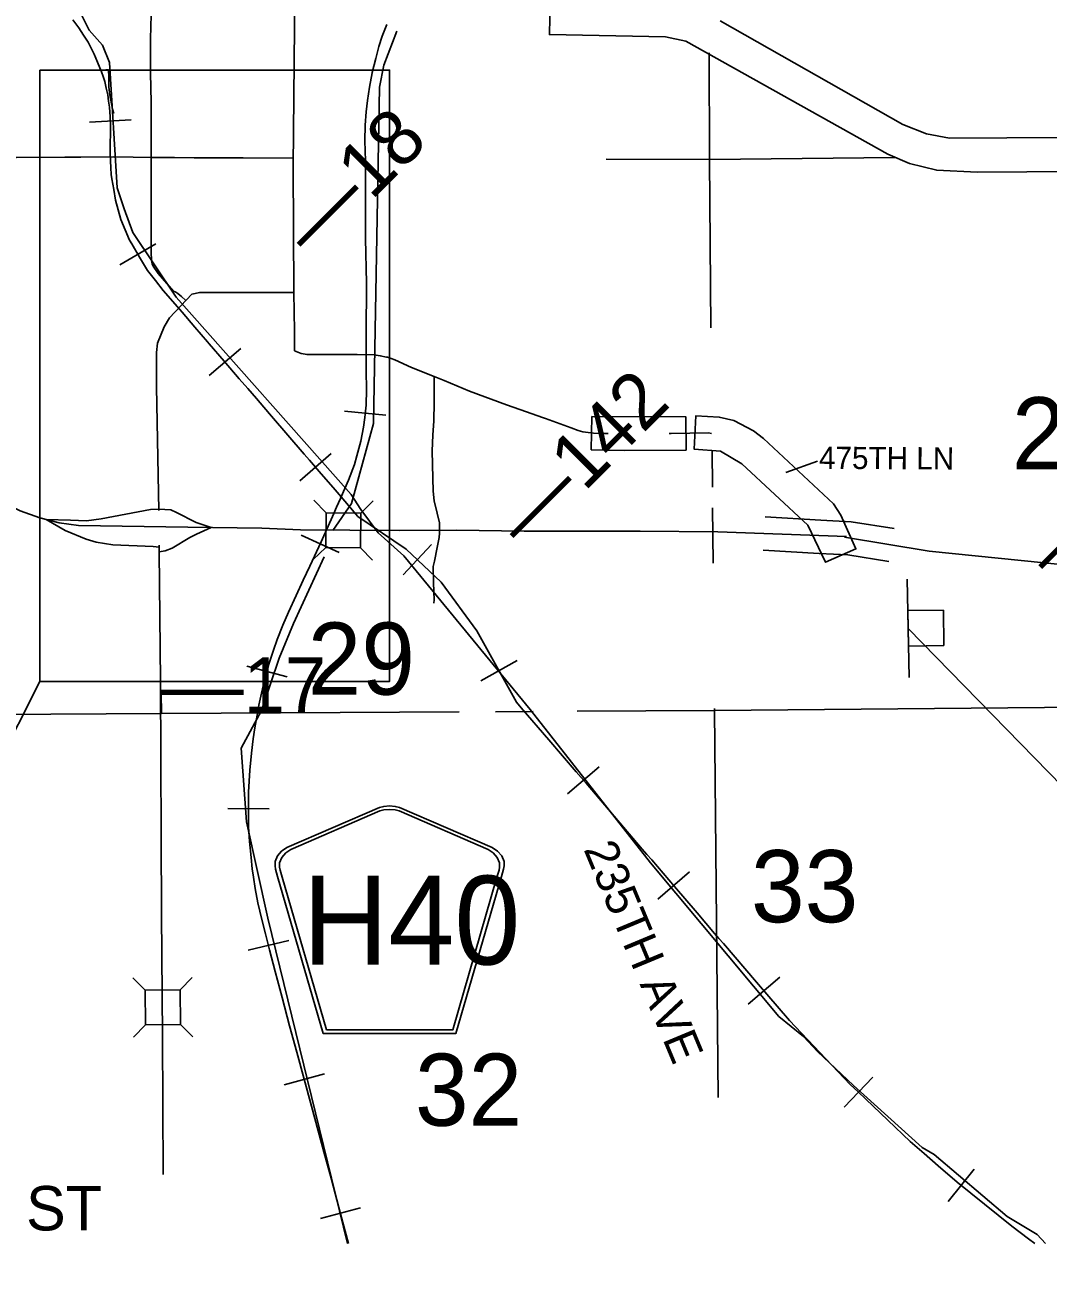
# Model space of a CAD drawing. Extents: x 10133 to 81668, y 5524 to 11018.
# Drawn here: x 18489.8 to 18720.3, y 8198.3 to 8478.4 of the extents above; entities that cross this region are included whole.
import ezdxf

# ---------------------------------------------------------------- set-up
doc = ezdxf.new("R2010")
doc.units = 0
for name, color, linetype in [('Default', 7, 'Continuous'), ('DisBoundDim', 7, 'Continuous'), ('DisCLMLOR', 7, 'Continuous'), ('DisCLMLSUR', 7, 'Continuous'), ('DsnShtRevisedText', 7, 'Continuous'), ('trf_Signal_(Temp)_Layout', 7, 'Continuous')]:
    doc.layers.add(name, color=color, linetype=linetype)

msp = doc.modelspace()

# ---------------------------------------------------------------- linework, layer by layer
at = {"layer": 'Default'}
for p, q in [((18504.33, 8456.54), (18513.69, 8457.07)), ((18511.2, 8424.34), (18519.28, 8429.08)), ((18531.29, 8399.4), (18538.41, 8405.51)), ((18571.11, 8390.47), (18561.78, 8391.37)), ((18551.72, 8375.73), (18558.81, 8381.86)), ((18661.23, 8377.6), (18668.35, 8380.11)), ((18557.64, 8368.53), (18554.91, 8371.33)), ((18559.14, 8364.52), (18563.36, 8370.6)), ((18559.14, 8364.52), (18563.36, 8370.6)), ((18565.47, 8368.44), (18568.26, 8371.18)), ((18560.57, 8359.59), (18552.05, 8363.49)), ((18557.56, 8360.7), (18554.76, 8357.97)), ((18574.99, 8354.52), (18581.4, 8361.36)), ((18565.38, 8360.62), (18568.12, 8357.82)), ((18548.83, 8331.54), (18539.77, 8333.95)), ((18592.5, 8330.65), (18600.69, 8335.22)), ((18612.02, 8305.22), (18619.15, 8311.31)), ((18544.84, 8301.82), (18535.47, 8301.9)), ((18632.36, 8281.49), (18639.48, 8287.59)), ((18549.21, 8272.16), (18540.1, 8269.94)), ((18516.91, 8260.98), (18514.12, 8263.72)), ((18524.73, 8261.04), (18527.48, 8263.83)), ((18652.73, 8257.77), (18659.84, 8263.89)), ((18516.97, 8253.15), (18514.23, 8250.36)), ((18524.8, 8253.22), (18527.59, 8250.47)), ((18557.24, 8242.1), (18548.2, 8239.62)), ((18674.32, 8234.57), (18680.8, 8241.35)), ((18697.77, 8213.34), (18703.66, 8220.64)), ((18565.4, 8211.89), (18556.34, 8209.49))]:
    msp.add_line(p, q, dxfattribs=at)
for points in [[(18549.96, 8829.52), (18550.05, 8805.91), (18550.08, 8784.02), (18550.7, 8682.54), (18550.52, 8671.29), (18550.52, 8648.11), (18550.42, 8612.38), (18550.55, 8600.55), (18550.42, 8588.37), (18550.39, 8561.4), (18550.49, 8516.33), (18550.49, 8477.93), (18550.25, 8446.49), (18550.39, 8418.13), (18529.16, 8418.16), (18527.4, 8417.73), (18522.35, 8412.45), (18521.12, 8410.42), (18519.69, 8406.72), (18519.42, 8404.63), (18519.45, 8396.89), (18519.92, 8368.99)], [(18377.81, 8580.32), (18418.01, 8548.19), (18499.93, 8484.11), (18502.3, 8481.16), (18504.29, 8477.22), (18507.26, 8473.87), (18508.86, 8469.93), (18510.53, 8441.72), (18512.12, 8436.99), (18514.11, 8431.67), (18523.83, 8417.09), (18563.25, 8372.62), (18565.44, 8369.27), (18569.4, 8363.96), (18575.14, 8358.84), (18603.64, 8324.17)], [(18377.81, 8580.32), (18418.01, 8548.19), (18499.93, 8484.11), (18502.3, 8481.16), (18504.29, 8477.22), (18507.26, 8473.87), (18508.86, 8469.93), (18510.53, 8441.72), (18512.12, 8436.99), (18514.11, 8431.67), (18523.83, 8417.09), (18563.25, 8372.62), (18565.44, 8369.27), (18569.4, 8363.96), (18575.14, 8358.84), (18603.64, 8324.17)], [(18816.05, 8445.98), (18704.28, 8445.21), (18695.21, 8445.66), (18689.09, 8447.21), (18684.18, 8449.31), (18638.68, 8474.75), (18634.09, 8475.7), (18607.96, 8476.25), (18608.14, 8483.75)], [(18646.39, 8479.35), (18687.6, 8455.98), (18692.87, 8453.87), (18698.1, 8452.88), (18827.11, 8453.63), (18830.92, 8454.32), (18837.18, 8457.2), (18882.24, 8482.55)], [(18500.59, 8479.53), (18501.96, 8477.75), (18502.99, 8476.14), (18504.02, 8474.54), (18504.71, 8473.19), (18505.4, 8471.85), (18506.16, 8469.99), (18507.03, 8467.88), (18507.39, 8466.79), (18507.76, 8465.7), (18508.11, 8464.17), (18508.46, 8462.64), (18508.65, 8461.27), (18508.84, 8459.9), (18508.96, 8457.69), (18509.09, 8455.48), (18509.03, 8453.42), (18509, 8452.26), (18508.96, 8451.09), (18509, 8449.43), (18509.04, 8447.78), (18509.13, 8446.23), (18509.21, 8444.69), (18509.37, 8443.76), (18509.78, 8441.36), (18510.19, 8438.96), (18510.81, 8436.78), (18511.42, 8434.6), (18512.39, 8432.26), (18513.36, 8429.93), (18513.84, 8429.09), (18515.61, 8426.08), (18517.37, 8423.07), (18519.17, 8420.84), (18520.96, 8418.6), (18524.18, 8414.94), (18524.69, 8414.31), (18525.21, 8413.68), (18528.07, 8410.35), (18530.94, 8407.01), (18531.33, 8406.55), (18534.69, 8402.64), (18538.06, 8398.72), (18540, 8396.5), (18541.95, 8394.28), (18543.63, 8392.29), (18545.31, 8390.31), (18549.01, 8386.03), (18552.71, 8381.75), (18553.9, 8380.37), (18556.56, 8377.29), (18559.22, 8374.22), (18560.12, 8373.15), (18561.02, 8372.09), (18564.75, 8367.68), (18575.7, 8360.28), (18583.59, 8352.89), (18591.57, 8341.93), (18600.56, 8325.83), (18601.6, 8324.59), (18607.8, 8317.36), (18614, 8310.13), (18616.19, 8307.56), (18622.51, 8300.16), (18628.84, 8292.75), (18629.92, 8291.52), (18631, 8290.29), (18636.1, 8284.33), (18641.2, 8278.37), (18643.18, 8276.06), (18645.16, 8273.75), (18646.15, 8272.61), (18647.14, 8271.46), (18654.6, 8262.79), (18662.05, 8254.12), (18668.89, 8246.91), (18675.73, 8239.71), (18677.47, 8238.05), (18679.2, 8236.39), (18684.21, 8231.65), (18689.22, 8226.9), (18692.38, 8224.14), (18695.54, 8221.38), (18699.79, 8217.74), (18705.95, 8212.77), (18712.11, 8207.8), (18715.88, 8204.97), (18717.33, 8203.88)], [(18500.59, 8479.53), (18501.96, 8477.75), (18502.99, 8476.14), (18504.02, 8474.54), (18504.71, 8473.19), (18505.4, 8471.85), (18506.16, 8469.99), (18507.03, 8467.88), (18507.39, 8466.79), (18507.76, 8465.7), (18508.11, 8464.17), (18508.46, 8462.64), (18508.65, 8461.27), (18508.84, 8459.9), (18508.96, 8457.69), (18509.09, 8455.48), (18509.03, 8453.42), (18509, 8452.26), (18508.96, 8451.09), (18509, 8449.43), (18509.04, 8447.78), (18509.13, 8446.23), (18509.21, 8444.69), (18509.37, 8443.76), (18509.78, 8441.36), (18510.19, 8438.96), (18510.81, 8436.78), (18511.42, 8434.6), (18512.39, 8432.26), (18513.36, 8429.93), (18513.84, 8429.09), (18515.61, 8426.08), (18517.37, 8423.07), (18519.17, 8420.84), (18520.96, 8418.6), (18524.18, 8414.94), (18524.69, 8414.31), (18525.21, 8413.68), (18528.07, 8410.35), (18530.94, 8407.01), (18531.33, 8406.55), (18534.69, 8402.64), (18538.06, 8398.72), (18540, 8396.5), (18541.95, 8394.28), (18543.63, 8392.29), (18545.31, 8390.31), (18549.01, 8386.03), (18552.71, 8381.75), (18553.9, 8380.37), (18556.56, 8377.29), (18559.22, 8374.22), (18560.12, 8373.15), (18561.02, 8372.09), (18564.75, 8367.68), (18575.7, 8360.28), (18583.59, 8352.89), (18591.57, 8341.93), (18600.56, 8325.83), (18601.6, 8324.59), (18607.8, 8317.36), (18614, 8310.13), (18616.19, 8307.56), (18622.51, 8300.16), (18628.84, 8292.75), (18629.92, 8291.52), (18631, 8290.29), (18636.1, 8284.33), (18641.2, 8278.37), (18643.18, 8276.06), (18645.16, 8273.75), (18646.15, 8272.61), (18647.14, 8271.46), (18654.6, 8262.79), (18662.05, 8254.12), (18668.89, 8246.91), (18675.73, 8239.71), (18677.47, 8238.05), (18679.2, 8236.39), (18684.21, 8231.65), (18689.22, 8226.9), (18692.38, 8224.14), (18695.54, 8221.38), (18699.79, 8217.74), (18705.95, 8212.77), (18712.11, 8207.8), (18715.88, 8204.97), (18717.33, 8203.88)], [(18500.59, 8479.53), (18501.96, 8477.75), (18502.99, 8476.14), (18504.02, 8474.54), (18504.71, 8473.19), (18505.4, 8471.85), (18506.16, 8469.99), (18507.03, 8467.88), (18507.39, 8466.79), (18507.76, 8465.7), (18508.11, 8464.17), (18508.46, 8462.64), (18508.65, 8461.27), (18508.84, 8459.9), (18508.96, 8457.69), (18509.09, 8455.48), (18509.03, 8453.42), (18509, 8452.26), (18508.96, 8451.09), (18509, 8449.43), (18509.04, 8447.78), (18509.13, 8446.23), (18509.21, 8444.69), (18509.37, 8443.76), (18509.78, 8441.36), (18510.19, 8438.96), (18510.81, 8436.78), (18511.42, 8434.6), (18512.39, 8432.26), (18513.36, 8429.93), (18513.84, 8429.09), (18515.61, 8426.08), (18517.37, 8423.07), (18519.17, 8420.84), (18520.96, 8418.6), (18524.18, 8414.94), (18524.69, 8414.31), (18525.21, 8413.68), (18528.07, 8410.35), (18530.94, 8407.01), (18531.33, 8406.55), (18534.69, 8402.64), (18538.06, 8398.72), (18540, 8396.5), (18541.95, 8394.28), (18543.63, 8392.29), (18545.31, 8390.31), (18549.01, 8386.03), (18552.71, 8381.75), (18553.9, 8380.37), (18556.56, 8377.29), (18559.22, 8374.22), (18560.12, 8373.15), (18561.02, 8372.09), (18564.75, 8367.68), (18575.7, 8360.28), (18583.59, 8352.89), (18591.57, 8341.93), (18600.56, 8325.83), (18601.6, 8324.59), (18607.8, 8317.36), (18614, 8310.13), (18616.19, 8307.56), (18622.51, 8300.16), (18628.84, 8292.75), (18629.92, 8291.52), (18631, 8290.29), (18636.1, 8284.33), (18641.2, 8278.37), (18643.18, 8276.06), (18645.16, 8273.75), (18646.15, 8272.61), (18647.14, 8271.46), (18654.6, 8262.79), (18662.05, 8254.12), (18668.89, 8246.91), (18675.73, 8239.71), (18677.47, 8238.05), (18679.2, 8236.39), (18684.21, 8231.65), (18689.22, 8226.9), (18692.38, 8224.14), (18695.54, 8221.38), (18699.79, 8217.74), (18705.95, 8212.77), (18712.11, 8207.8), (18715.88, 8204.97), (18717.33, 8203.88)], [(18518.23, 8448.58), (18518.2, 8456.57), (18518.2, 8458.37), (18518.2, 8460.95), (18518.11, 8467.64), (18518.11, 8468.24), (18518.05, 8475.25), (18518.21, 8480.66)], [(18562.65, 8203.88), (18560.89, 8210.6), (18558.86, 8218.27), (18557.32, 8223.68), (18554.37, 8234.82), (18551.03, 8247.01), (18549.42, 8252.94), (18547.75, 8259.33), (18546.15, 8265.2), (18544.9, 8270.04), (18544.02, 8273.68), (18543.16, 8276.89), (18542.28, 8280.6), (18541.69, 8283.87), (18541.26, 8286.4), (18540.97, 8288.33), (18540.74, 8290.82), (18540.41, 8294.46), (18540.18, 8297.73), (18540.15, 8301.5), (18540.18, 8305.57), (18540.45, 8310.55), (18540.84, 8314.38), (18541.2, 8317.59), (18541.56, 8320.08), (18542.08, 8322.93), (18542.48, 8325.16), (18543.07, 8327.85), (18543.79, 8330.83), (18544.74, 8334.4), (18545.75, 8337.55), (18546.64, 8339.94), (18547.92, 8343.22), (18549.19, 8346.13), (18550.87, 8349.87), (18552.44, 8353.32), (18553.98, 8356.45), (18556.5, 8361.96), (18559.36, 8368.32), (18560.01, 8369.76), (18560.86, 8371.7), (18561.02, 8372.09), (18562.66, 8375.85), (18564.01, 8379.36), (18564.59, 8381.32), (18565.45, 8384.63), (18566.04, 8387.81), (18566.33, 8389.99), (18566.43, 8390.73), (18566.63, 8392.76), (18566.76, 8396.27), (18566.69, 8400.46), (18566.66, 8403.64), (18566.66, 8408.36), (18566.66, 8411.37), (18566.73, 8417.47), (18566.76, 8420.22), (18566.53, 8430.31), (18566.53, 8433.33), (18566.51, 8441.6), (18566.5, 8447.78), (18566.4, 8452.27), (18566.43, 8455.81), (18566.66, 8458.82), (18566.95, 8461.38), (18567.41, 8464.36), (18568.02, 8467.64), (18568.04, 8467.7), (18568.82, 8470.85), (18569.51, 8473.57), (18570.3, 8475.89), (18571.35, 8478.51)], [(18562.65, 8203.88), (18560.89, 8210.6), (18558.86, 8218.27), (18557.32, 8223.68), (18554.37, 8234.82), (18551.03, 8247.01), (18549.42, 8252.94), (18547.75, 8259.33), (18546.15, 8265.2), (18544.9, 8270.04), (18544.02, 8273.68), (18543.16, 8276.89), (18542.28, 8280.6), (18541.69, 8283.87), (18541.26, 8286.4), (18540.97, 8288.33), (18540.74, 8290.82), (18540.41, 8294.46), (18540.18, 8297.73), (18540.15, 8301.5), (18540.18, 8305.57), (18540.45, 8310.55), (18540.84, 8314.38), (18541.2, 8317.59), (18541.56, 8320.08), (18542.08, 8322.93), (18542.48, 8325.16), (18543.07, 8327.85), (18543.79, 8330.83), (18544.74, 8334.4), (18545.75, 8337.55), (18546.64, 8339.94), (18547.92, 8343.22), (18549.19, 8346.13), (18550.87, 8349.87), (18552.44, 8353.32), (18553.98, 8356.45), (18556.5, 8361.96), (18559.36, 8368.32), (18560.01, 8369.76), (18560.86, 8371.7), (18561.02, 8372.09), (18562.66, 8375.85), (18564.01, 8379.36), (18564.59, 8381.32), (18565.45, 8384.63), (18566.04, 8387.81), (18566.33, 8389.99), (18566.43, 8390.73), (18566.63, 8392.76), (18566.76, 8396.27), (18566.69, 8400.46), (18566.66, 8403.64), (18566.66, 8408.36), (18566.66, 8411.37), (18566.73, 8417.47), (18566.76, 8420.22), (18566.53, 8430.31), (18566.53, 8433.33), (18566.51, 8441.6), (18566.5, 8447.78), (18566.4, 8452.27), (18566.43, 8455.81), (18566.66, 8458.82), (18566.95, 8461.38), (18567.41, 8464.36), (18568.02, 8467.64), (18568.04, 8467.7), (18568.82, 8470.85), (18569.51, 8473.57), (18570.3, 8475.89), (18571.35, 8478.51)], [(18562.65, 8203.88), (18560.89, 8210.6), (18558.86, 8218.27), (18557.32, 8223.68), (18554.37, 8234.82), (18551.03, 8247.01), (18549.42, 8252.94), (18547.75, 8259.33), (18546.15, 8265.2), (18544.9, 8270.04), (18544.02, 8273.68), (18543.16, 8276.89), (18542.28, 8280.6), (18541.69, 8283.87), (18541.26, 8286.4), (18540.97, 8288.33), (18540.74, 8290.82), (18540.41, 8294.46), (18540.18, 8297.73), (18540.15, 8301.5), (18540.18, 8305.57), (18540.45, 8310.55), (18540.84, 8314.38), (18541.2, 8317.59), (18541.56, 8320.08), (18542.08, 8322.93), (18542.48, 8325.16), (18543.07, 8327.85), (18543.79, 8330.83), (18544.74, 8334.4), (18545.75, 8337.55), (18546.64, 8339.94), (18547.92, 8343.22), (18549.19, 8346.13), (18550.87, 8349.87), (18552.44, 8353.32), (18553.98, 8356.45), (18556.5, 8361.96), (18559.36, 8368.32), (18560.01, 8369.76), (18560.86, 8371.7), (18561.02, 8372.09), (18562.66, 8375.85), (18564.01, 8379.36), (18564.59, 8381.32), (18565.45, 8384.63), (18566.04, 8387.81), (18566.33, 8389.99), (18566.43, 8390.73), (18566.63, 8392.76), (18566.76, 8396.27), (18566.69, 8400.46), (18566.66, 8403.64), (18566.66, 8408.36), (18566.66, 8411.37), (18566.73, 8417.47), (18566.76, 8420.22), (18566.53, 8430.31), (18566.53, 8433.33), (18566.51, 8441.6), (18566.5, 8447.78), (18566.4, 8452.27), (18566.43, 8455.81), (18566.66, 8458.82), (18566.95, 8461.38), (18567.41, 8464.36), (18568.02, 8467.64), (18568.04, 8467.7), (18568.82, 8470.85), (18569.51, 8473.57), (18570.3, 8475.89), (18571.35, 8478.51)], [(18563.36, 8370.6), (18568.33, 8388.62), (18569.66, 8464.4), (18570.63, 8469.33), (18573.57, 8477.04)], [(18563.36, 8370.6), (18568.33, 8388.62), (18569.66, 8464.4), (18570.63, 8469.33), (18573.57, 8477.04)], [(18643.93, 8472.13), (18643.98, 8448.12)], [(18508, 8468.27), (18508.62, 8468.27)], [(18509.8, 8458.44), (18509.49, 8459.45), (18508.91, 8462.66), (18508.66, 8464.42), (18508.66, 8466.67), (18508.62, 8468.27)], [(18458.15, 8448.9), (18467.2, 8448.77), (18468.06, 8448.76), (18468.88, 8448.75), (18479.25, 8448.66), (18487.78, 8448.58), (18487.91, 8448.58), (18498.78, 8448.63), (18502.4, 8448.65), (18509.8, 8448.68), (18514.2, 8448.63), (18518.23, 8448.58)], [(18526.03, 8416.33), (18525.09, 8417.2), (18524.66, 8417.56), (18524.22, 8417.9), (18523.75, 8418.2), (18523.27, 8418.47), (18519.82, 8422.44), (18518.67, 8424.05), (18518.42, 8424.6), (18518.33, 8425.37), (18518.2, 8427.26), (18518.21, 8428.91), (18518.23, 8432.93), (18518.2, 8437.15), (18518.21, 8438.67), (18518.23, 8447.69), (18518.23, 8448.58)], [(18518.23, 8448.58), (18523.52, 8448.52), (18527.95, 8448.51), (18534.12, 8448.5), (18537.78, 8448.49), (18538.99, 8448.49), (18550.25, 8448.4), (18550.25, 8448.4)], [(18620.73, 8448.18), (18643.98, 8448.12)], [(18643.98, 8448.12), (18685.75, 8448.57)], [(18643.98, 8448.12), (18644.33, 8410.2)], [(18550.38, 8418.13), (18550.38, 8418.13), (18550.49, 8409.39), (18550.52, 8407.18), (18550.53, 8405.03), (18552.03, 8404.41), (18553.36, 8404.13), (18555.7, 8404.13), (18561.12, 8404.13), (18564.67, 8404.13), (18568.49, 8404.1), (18569.82, 8403.89), (18571.28, 8403.58), (18571.45, 8403.55), (18573.15, 8402.99), (18576.88, 8401.24), (18581.97, 8399.2)], [(18581.92, 8348.13), (18581.98, 8348.91), (18581.98, 8348.93), (18581.8, 8352.72), (18581.77, 8356.39), (18582.04, 8357.59), (18582.66, 8360.67), (18583.09, 8362.92), (18583.18, 8363.94), (18583.18, 8364.59), (18583.15, 8366.22), (18582.69, 8368.44), (18582.01, 8371.21), (18581.77, 8373.37), (18581.67, 8376.27), (18581.52, 8382.5), (18581.67, 8385.98), (18581.89, 8389.25), (18581.91, 8389.89), (18581.98, 8392.67), (18582.01, 8398.65), (18581.97, 8399.2)], [(18581.97, 8399.2), (18584.21, 8398.31), (18589.92, 8395.9), (18598.27, 8392.85), (18602.78, 8391.27), (18606.4, 8390), (18607.06, 8389.77), (18612.81, 8387.62), (18614.39, 8387.02), (18615.5, 8386.72), (18617.88, 8386.44), (18620.18, 8386.4), (18621.19, 8386.38)], [(18624.9, 8382.57), (18617.39, 8382.7), (18617.53, 8390.19), (18638.68, 8390.15), (18638.72, 8382.65), (18624.9, 8382.57)], [(18666.17, 8365.69), (18651.3, 8379.5), (18646.47, 8382.37), (18640.58, 8382.83), (18640.93, 8390.32), (18646.21, 8390.07), (18649.51, 8389.28), (18653.9, 8387), (18656.15, 8385.22), (18671.91, 8370.51), (18673.63, 8367.99), (18677.01, 8360.38), (18670.15, 8357.35), (18666.17, 8365.69)], [(18634.95, 8386.37), (18635.36, 8386.38), (18643.77, 8386.5), (18644.5, 8386.4)], [(18644.58, 8382.65), (18644.66, 8374.26)], [(18519.96, 8369.29), (18518.11, 8369.25), (18506.94, 8367.13), (18503.69, 8366.7), (18500.05, 8366.82), (18494.59, 8366.99)], [(18531.71, 8365.22), (18528.35, 8366.35), (18523.9, 8368.6), (18522.63, 8369.14), (18519.96, 8369.29)], [(18644.71, 8369.64), (18644.82, 8357.15)], [(18494.6, 8366.99), (18498.87, 8364.48), (18503.59, 8362.6), (18505.81, 8361.92), (18509.62, 8361.31), (18518.69, 8360.92), (18520.05, 8360.79)], [(18656.54, 8367.58), (18669.11, 8366.83), (18675.96, 8366.46), (18685.64, 8364.96)], [(18520.06, 8359.69), (18521.35, 8359.91), (18522.97, 8360.52), (18526.97, 8362.96), (18528.47, 8363.69), (18531.71, 8365.22)], [(18656.34, 8363.87), (18656.33, 8363.87)], [(18543.06, 8323.99), (18547.09, 8335.78), (18550.32, 8343.57), (18557.18, 8358.59)], [(18543.06, 8323.99), (18547.09, 8335.78), (18550.32, 8343.57), (18557.18, 8358.59)], [(18656.13, 8360.09), (18668.72, 8359.33), (18675.19, 8359), (18684.38, 8357.56)], [(18520.48, 8327.97), (18520.57, 8323.3)], [(18645.12, 8324.41), (18645.13, 8323.93)], [(18645.13, 8323.93), (18769.03, 8325.06)], [(18395.75, 8322.57), (18520.57, 8323.3)], [(18520.57, 8323.3), (18587.64, 8323.64)], [(18562.49, 8203.88), (18544.54, 8277.19), (18539.74, 8298.89), (18538.51, 8315.46), (18543.06, 8323.99)], [(18562.49, 8203.88), (18544.54, 8277.19), (18539.74, 8298.89), (18538.51, 8315.46), (18543.06, 8323.99)], [(18595.77, 8323.68), (18604.31, 8323.73)], [(18603.64, 8324.17), (18630.74, 8289.68), (18659.65, 8255.04), (18665.18, 8250.52), (18668.35, 8247.17), (18676.46, 8239.5), (18691.89, 8225.53), (18694.66, 8223.96), (18711.08, 8210), (18717.8, 8205.88), (18719.7, 8203.88)], [(18603.64, 8324.17), (18630.74, 8289.68), (18659.65, 8255.04), (18665.18, 8250.52), (18668.35, 8247.17), (18676.46, 8239.5), (18691.89, 8225.53), (18694.66, 8223.96), (18711.08, 8210), (18717.8, 8205.88), (18719.7, 8203.88)], [(18614.19, 8323.78), (18645.13, 8323.93)], [(18645.93, 8236.79), (18645.13, 8323.93)]]:
    msp.add_lwpolyline(points, dxfattribs=at)
for points in [[(18557.64, 8368.53), (18565.47, 8368.44), (18565.38, 8360.62), (18557.56, 8360.7)], [(18556.96, 8251.2), (18546.72, 8286.56), (18546.23, 8288.21), (18546.14, 8288.94), (18546.14, 8289.92), (18546.67, 8291.21), (18547.58, 8292.27), (18548.78, 8293.11), (18569.69, 8302.15), (18570.63, 8302.35), (18571.93, 8302.47), (18573.23, 8302.35), (18574.17, 8302.15), (18595.08, 8293.11), (18596.28, 8292.27), (18597.19, 8291.21), (18597.72, 8289.92), (18597.72, 8288.94), (18597.63, 8288.21), (18597.14, 8286.56), (18586.9, 8251.2)], [(18557.69, 8251.99), (18547.73, 8286.4), (18547.26, 8287.98), (18547.17, 8288.69), (18547.17, 8289.63), (18547.68, 8290.86), (18548.55, 8291.88), (18549.7, 8292.68), (18569.78, 8301.36), (18570.68, 8301.56), (18571.93, 8301.67), (18573.18, 8301.56), (18574.08, 8301.36), (18594.16, 8292.68), (18595.3, 8291.88), (18596.18, 8290.86), (18596.69, 8289.63), (18596.69, 8288.69), (18596.6, 8287.98), (18596.13, 8286.4), (18586.17, 8251.99)], [(18516.97, 8253.15), (18516.91, 8260.98), (18524.73, 8261.04), (18524.8, 8253.22)]]:
    msp.add_lwpolyline(points, close=True, dxfattribs=at)
at = {"layer": 'DisBoundDim'}
for p, q in [((18688.58, 8353.53), (18688.96, 8331.4)), ((18688.7, 8346.47), (18696.7, 8346.6)), ((18696.7, 8346.6), (18696.84, 8338.61)), ((18688.84, 8338.47), (18696.84, 8338.61))]:
    msp.add_line(p, q, dxfattribs=at)
at = {"layer": 'DisCLMLOR'}
for p, q in [((18688.7, 8346.47), (18696.7, 8346.6)), ((18688.7, 8346.47), (18696.7, 8346.6)), ((18688.7, 8346.47), (18696.7, 8346.6)), ((18688.7, 8346.47), (18696.7, 8346.6)), ((18688.84, 8338.47), (18688.7, 8346.47)), ((18688.84, 8338.47), (18688.7, 8346.47)), ((18688.84, 8338.47), (18688.7, 8346.47)), ((18688.84, 8338.47), (18688.7, 8346.47)), ((18696.7, 8346.6), (18696.84, 8338.61)), ((18696.7, 8346.6), (18696.84, 8338.61)), ((18696.7, 8346.6), (18696.84, 8338.61)), ((18696.7, 8346.6), (18696.84, 8338.61)), ((18696.84, 8338.61), (18688.84, 8338.47)), ((18696.84, 8338.61), (18688.84, 8338.47)), ((18696.84, 8338.61), (18688.84, 8338.47)), ((18696.84, 8338.61), (18688.84, 8338.47))]:
    msp.add_line(p, q, dxfattribs=at)
at = {"layer": 'DisCLMLSUR'}
msp.add_line((18688.77, 8342.47), (18729.58, 8300.61), dxfattribs=at)
at = {"layer": 'DsnShtRevisedText'}
msp.add_lwpolyline([(18724.56, 8356.69), (18693.53, 8359.83), (18674.4, 8363.04)], dxfattribs=at)
at = {"layer": 'trf_Signal_(Temp)_Layout'}
msp.add_line((18379.79, 8106.8), (18493.16, 8330.51), dxfattribs=at)
msp.add_lwpolyline([(18493.16, 8468.23), (18571.93, 8468.23), (18571.93, 8330.51), (18493.16, 8330.51)], close=True, dxfattribs=at)
for points in [[(18377.81, 8439.26), (18378.06, 8439.12), (18452.75, 8391.47), (18484.36, 8371.19), (18488.75, 8368.94), (18493.15, 8367.35), (18497.47, 8366.26), (18501.89, 8365.65), (18526.51, 8365.29)], [(18526.51, 8365.3), (18543.15, 8365.03), (18551.87, 8364.68), (18574.12, 8364.54), (18587.03, 8364.61), (18602.25, 8364.33), (18628.38, 8364.4), (18645.89, 8364.22), (18674.84, 8363.15)], [(18520.04, 8361.25), (18520.06, 8359.69), (18520.31, 8330.62), (18520.53, 8278.09), (18520.8, 8250.65), (18520.95, 8219.42)]]:
    msp.add_lwpolyline(points, dxfattribs=at)

# ---------------------------------------------------------------- texts
at = {"layer": 'Default'}
for s, height, rotation, p in [('‒‒18', 12.5, 45, (18554.7, 8425.62)), ('‒‒142', 12.5, 45, (18602.69, 8359.98)), ('28', 16.25, 0.0094, (18712.14, 8378.29)), ('‒‒143', 12.5, 45, (18721.77, 8353.01)), ('475TH LN', 5, 359.7, (18668.66, 8378.41)), ('29', 16.25, 0.0086, (18553.49, 8327.53)), ('235TH AVE', 7.5, 292.6039, (18615.58, 8292.73)), ('33', 16.25, 0.0086, (18653.36, 8276.26)), ('32', 16.25, 0.0079, (18577.66, 8230.41))]:
    msp.add_text(s, height=height, rotation=rotation, dxfattribs=at).set_placement(p)
for s, height, p in [('‒‒17', 12.5, (18520.46, 8323.46)), ('H40', 20, (18552.34, 8266.73)), ('460TH ST', 10, (18446.2, 8206.84))]:
    msp.add_text(s, height=height, dxfattribs=at).set_placement(p)

doc.saveas('drawing.dxf')
